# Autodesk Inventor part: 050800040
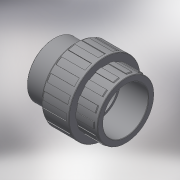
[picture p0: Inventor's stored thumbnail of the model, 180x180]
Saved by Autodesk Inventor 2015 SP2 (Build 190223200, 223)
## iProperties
Created: 2017-10
Part Number: 050800040
Material: Generic
Description: PLASSON UNION+O RING-CEM PVC 40
Document SubType Name: Modeling
Designer: Кирилл
Density: 1 g/cm^3
Appearance: Default
Author: Кирилл
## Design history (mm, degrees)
derived "050800.ipt"
feature "Solid1::050800.ipt"
tag "TaggingFeature1"
body "Solid1"
other parameters: "d0" = 67, "d5" = 48, "d7" = 51.2, "d8" = 66, "d9" = 26, "d10" = 26, "d11" = 36, "d12" = 38, "d14" = 19.5, "d15" = 19.5, "d16" = 13.5, "d17" = 2.6, "d19" = 64.68, "d20" = 2.6, "d21" = 1.98, "d25" = 6.6, "d26" = 3.3, "d27" = 22.86, "d28" = 0, "d32" = 6.6, "d33" = 3.3, "d35" = 0, "d39" = 0.4, "d45" = 0.6, "d49" = 360 deg, "d51" = 0.66, "d55" = 360 deg, "E_" = 66, "H_" = 67, "l_" = 26, "l_1" = 26, "Z_" = 15, "d13" = 15, "d24" = 25.4, "d40" = 0.6, "d44" = 0.66
